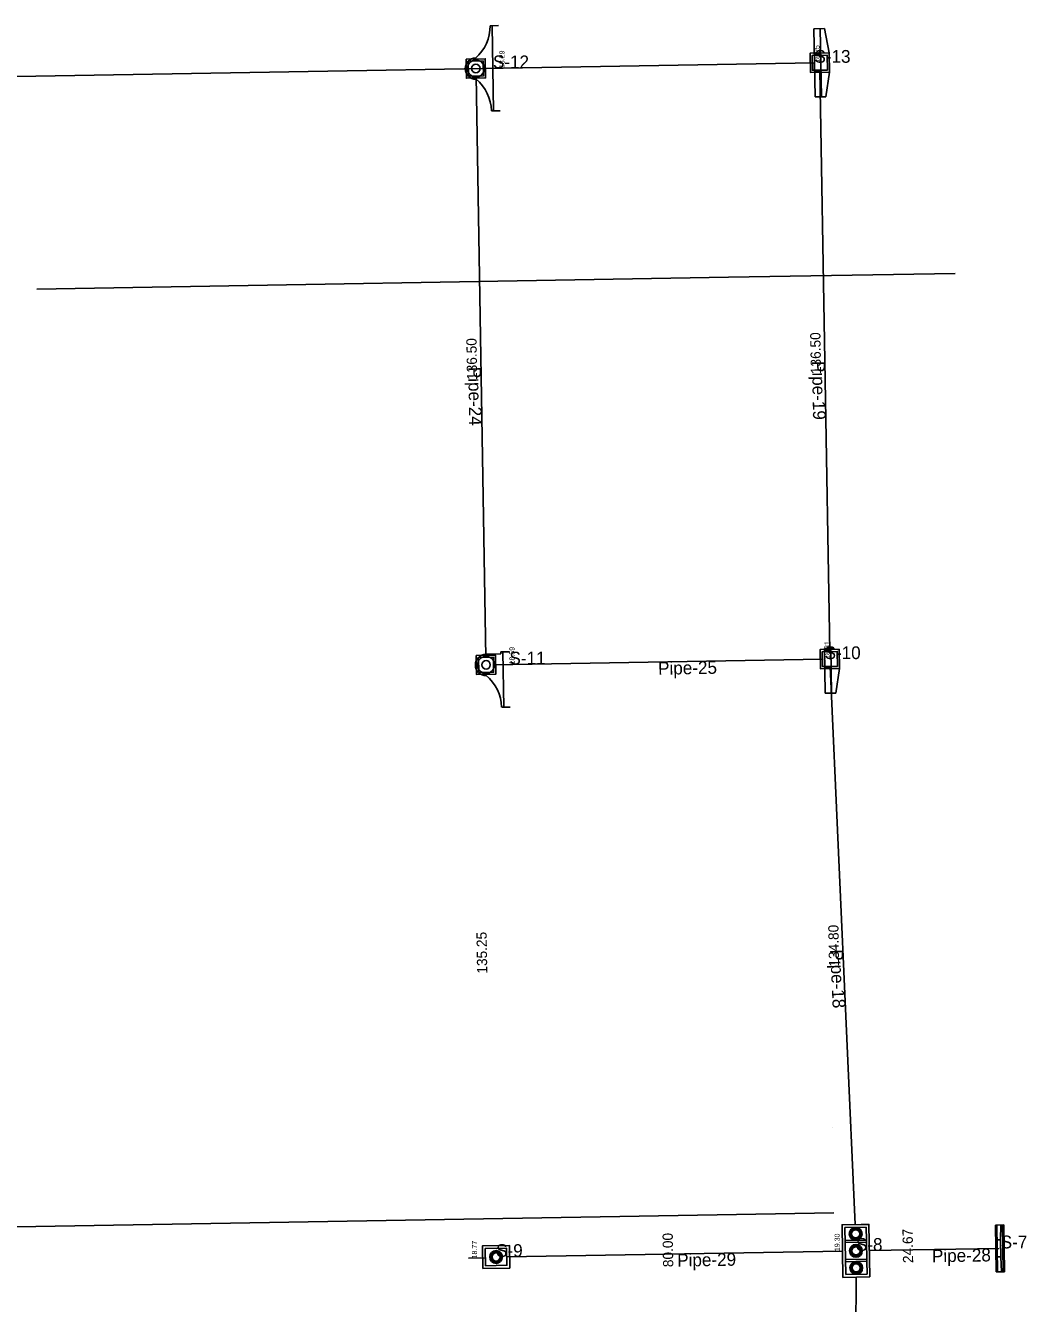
# Model space of a CAD drawing. Extents: x 925371 to 925937, y 853654 to 858024.
# Drawn here: x 925658.7 to 925893.7, y 853987.9 to 854287.9 of the extents above; entities that cross this region are included whole.
import ezdxf

# ---------------------------------------------------------------- set-up
doc = ezdxf.new("R2010")
doc.units = 0
for name, color, linetype in [('Endwall', 7, 'Continuous'), ('GPKDrBack_dp', 7, 'Continuous'), ('GPKDrBottom_dp', 7, 'Continuous'), ('GPKDrCellIns_dp', 7, 'Continuous'), ('GPKDrCentroid_dp', 7, 'Continuous'), ('GPKDrFront_dp', 7, 'Continuous'), ('GPKDrPipe_dp', 7, 'Continuous'), ('GPKDrPipeCir_dp', 7, 'Continuous'), ('InletBottomJ', 7, 'Continuous'), ('InletBottomP', 7, 'Continuous'), ('InletCurb', 7, 'Continuous'), ('Manhole', 7, 'Continuous'), ('Miscellaneous5', 7, 'Continuous'), ('Miscellaneous6', 7, 'Continuous'), ('NonPlottingEle_dp', 7, 'Continuous'), ('PipeCulvert', 7, 'Continuous')]:
    doc.layers.add(name, color=color, linetype=linetype)

msp = doc.modelspace()

# ---------------------------------------------------------------- linework, layer by layer
at = {"layer": 'Endwall'}
for p, q in [((925886.44, 854006.34), (925888.44, 854006.38)), ((925886.44, 854006.34), (925886.62, 853995.34)), ((925886.77, 854006.35), (925886.96, 853995.35)), ((925887.69, 854006.36), (925887.66, 854002.86)), ((925888.1, 854006.37), (925888.29, 853995.37)), ((925888.44, 854006.38), (925888.62, 853995.38)), ((925886.83, 854002.85), (925887.66, 854002.86)), ((925887.66, 854002.86), (925887.73, 853998.86)), ((925886.9, 853998.85), (925887.73, 853998.86)), ((925887.73, 853998.86), (925887.88, 853995.36)), ((925886.62, 853995.34), (925888.62, 853995.38))]:
    msp.add_line(p, q, dxfattribs=at)
at = {"layer": 'GPKDrBack_dp'}
for p, q in [((925846.96, 854279.21), (925846.96, 854279.21)), ((925847.46, 854279.22), (925847.46, 854279.22)), ((925761.97, 854277.76), (925761.97, 854277.76)), ((925762.72, 854277.78), (925762.72, 854277.78)), ((925764.35, 854137.78), (925764.35, 854137.78)), ((925765.1, 854137.8), (925765.1, 854137.8)), ((925849.34, 854139.23), (925849.34, 854139.23)), ((925849.84, 854139.24), (925849.84, 854139.24)), ((925852.14, 854004.26), (925852.14, 854004.26)), ((925852.2, 854000.26), (925852.2, 854000.26)), ((925886.86, 854000.85), (925886.86, 854000.85)), ((925769.24, 853997.35), (925769.24, 853997.35)), ((925769.25, 853996.85), (925769.25, 853996.85)), ((925852.27, 853996.26), (925852.27, 853996.26))]:
    msp.add_line(p, q, dxfattribs=at)
at = {"layer": 'GPKDrBottom_dp'}
for p, q in [((925762.69, 854279.53), (925762.69, 854279.53)), ((925763.03, 854279.2), (925763.03, 854279.2)), ((925764.44, 854279.81), (925764.44, 854279.81)), ((925764.44, 854279.56), (925764.44, 854279.56)), ((925765.86, 854279.24), (925765.86, 854279.24)), ((925766.19, 854279.59), (925766.19, 854279.59)), ((925843.43, 854280.9), (925843.43, 854280.9)), ((925843.43, 854280.9), (925843.43, 854280.9)), ((925843.46, 854279.15), (925843.46, 854279.15)), ((925843.46, 854279.15), (925843.46, 854279.15)), ((925845.18, 854280.93), (925845.18, 854280.93)), ((925845.18, 854280.93), (925845.18, 854280.93)), ((925845.21, 854279.18), (925845.21, 854279.18)), ((925845.21, 854279.18), (925845.21, 854279.18)), ((925846.93, 854280.96), (925846.93, 854280.96)), ((925846.93, 854280.96), (925846.93, 854280.96)), ((925846.96, 854279.21), (925846.96, 854279.21)), ((925846.96, 854279.21), (925846.96, 854279.21)), ((925762.47, 854277.77), (925762.47, 854277.77)), ((925762.72, 854277.78), (925762.72, 854277.78)), ((925762.75, 854276.03), (925762.75, 854276.03)), ((925763.08, 854276.37), (925763.08, 854276.37)), ((925764.47, 854277.81), (925764.47, 854277.81)), ((925764.47, 854277.81), (925764.47, 854277.81)), ((925764.5, 854276.06), (925764.5, 854276.06)), ((925764.51, 854275.81), (925764.51, 854275.81)), ((925765.91, 854276.42), (925765.91, 854276.42)), ((925766.22, 854277.84), (925766.22, 854277.84)), ((925766.25, 854276.09), (925766.25, 854276.09)), ((925766.47, 854277.84), (925766.47, 854277.84)), ((925843.49, 854277.4), (925843.49, 854277.4)), ((925843.49, 854277.4), (925843.49, 854277.4)), ((925845.24, 854277.43), (925845.24, 854277.43)), ((925845.24, 854277.43), (925845.24, 854277.43)), ((925846.99, 854277.46), (925846.99, 854277.46)), ((925846.99, 854277.46), (925846.99, 854277.46)), ((925845.81, 854140.92), (925845.81, 854140.92)), ((925845.81, 854140.92), (925845.81, 854140.92)), ((925847.56, 854140.95), (925847.56, 854140.95)), ((925847.56, 854140.95), (925847.56, 854140.95)), ((925849.31, 854140.98), (925849.31, 854140.98)), ((925849.31, 854140.98), (925849.31, 854140.98)), ((925764.85, 854137.79), (925764.85, 854137.79)), ((925765.07, 854139.55), (925765.07, 854139.55)), ((925765.1, 854137.8), (925765.1, 854137.8)), ((925765.41, 854139.22), (925765.41, 854139.22)), ((925766.82, 854139.83), (925766.82, 854139.83)), ((925766.82, 854139.58), (925766.82, 854139.58)), ((925766.85, 854137.83), (925766.85, 854137.83)), ((925766.85, 854137.83), (925766.85, 854137.83)), ((925768.24, 854139.27), (925768.24, 854139.27)), ((925768.57, 854139.61), (925768.57, 854139.61)), ((925768.6, 854137.86), (925768.6, 854137.86)), ((925768.85, 854137.86), (925768.85, 854137.86)), ((925845.84, 854139.17), (925845.84, 854139.17)), ((925845.84, 854139.17), (925845.84, 854139.17)), ((925847.59, 854139.2), (925847.59, 854139.2)), ((925847.59, 854139.2), (925847.59, 854139.2)), ((925849.34, 854139.23), (925849.34, 854139.23)), ((925849.34, 854139.23), (925849.34, 854139.23)), ((925849.37, 854137.48), (925849.37, 854137.48)), ((925849.37, 854137.48), (925849.37, 854137.48)), ((925765.13, 854136.05), (925765.13, 854136.05)), ((925765.46, 854136.39), (925765.46, 854136.39)), ((925766.88, 854136.08), (925766.88, 854136.08)), ((925766.89, 854135.83), (925766.89, 854135.83)), ((925768.29, 854136.44), (925768.29, 854136.44)), ((925768.63, 854136.11), (925768.63, 854136.11)), ((925845.87, 854137.42), (925845.87, 854137.42)), ((925845.87, 854137.42), (925845.87, 854137.42)), ((925847.62, 854137.45), (925847.62, 854137.45)), ((925847.62, 854137.45), (925847.62, 854137.45)), ((925852.64, 854004.27), (925852.64, 854004.27)), ((925852.92, 854004.98), (925852.92, 854004.98)), ((925852.94, 854003.56), (925852.94, 854003.56)), ((925853.62, 854005.28), (925853.62, 854005.28)), ((925853.63, 854004.28), (925853.63, 854004.28)), ((925853.65, 854003.28), (925853.65, 854003.28)), ((925854.33, 854005), (925854.33, 854005)), ((925854.35, 854003.59), (925854.35, 854003.59)), ((925854.63, 854004.3), (925854.63, 854004.3)), ((925766.68, 854000.8), (925766.68, 854000.8)), ((925768.5, 853999.54), (925768.5, 853999.54)), ((925769.18, 854000.85), (925769.18, 854000.85)), ((925769.2, 853999.85), (925769.2, 853999.85)), ((925769.91, 853999.57), (925769.91, 853999.57)), ((925771.68, 854000.89), (925771.68, 854000.89)), ((925852.7, 854000.27), (925852.7, 854000.27)), ((925852.98, 854000.98), (925852.98, 854000.98)), ((925853.01, 853999.56), (925853.01, 853999.56)), ((925853.69, 854001.28), (925853.69, 854001.28)), ((925853.7, 854000.28), (925853.7, 854000.28)), ((925854.4, 854001), (925854.4, 854001)), ((925854.42, 853999.59), (925854.42, 853999.59)), ((925854.7, 854000.3), (925854.7, 854000.3)), ((925887.7, 854000.86), (925887.7, 854000.86)), ((925766.71, 853998.8), (925766.71, 853998.8)), ((925766.75, 853996.8), (925766.75, 853996.8)), ((925768.21, 853998.83), (925768.21, 853998.83)), ((925768.52, 853998.13), (925768.52, 853998.13)), ((925769.21, 853998.85), (925769.21, 853998.85)), ((925769.21, 853998.85), (925769.21, 853998.85)), ((925769.23, 853997.85), (925769.23, 853997.85)), ((925769.25, 853996.85), (925769.25, 853996.85)), ((925769.93, 853998.15), (925769.93, 853998.15)), ((925770.21, 853998.86), (925770.21, 853998.86)), ((925771.71, 853998.89), (925771.71, 853998.89)), ((925771.75, 853996.89), (925771.75, 853996.89)), ((925853.05, 853996.98), (925853.05, 853996.98)), ((925853.72, 853999.28), (925853.72, 853999.28)), ((925853.75, 853997.28), (925853.75, 853997.28)), ((925854.47, 853997), (925854.47, 853997)), ((925852.77, 853996.27), (925852.77, 853996.27)), ((925853.08, 853995.57), (925853.08, 853995.57)), ((925853.77, 853996.28), (925853.77, 853996.28)), ((925853.79, 853995.28), (925853.79, 853995.28)), ((925854.49, 853995.59), (925854.49, 853995.59)), ((925854.77, 853996.3), (925854.77, 853996.3))]:
    msp.add_line(p, q, dxfattribs=at)
at = {"layer": 'GPKDrCellIns_dp'}
for p, q in [((925843.96, 854279.16), (925843.96, 854279.16)), ((925845.21, 854279.18), (925845.21, 854279.18)), ((925764.47, 854277.81), (925764.47, 854277.81)), ((925769.97, 854277.9), (925769.97, 854277.9)), ((925766.85, 854137.83), (925766.85, 854137.83)), ((925772.35, 854137.92), (925772.35, 854137.92)), ((925846.34, 854139.18), (925846.34, 854139.18)), ((925847.59, 854139.2), (925847.59, 854139.2)), ((925853.63, 854004.28), (925853.63, 854004.28)), ((925853.7, 854000.28), (925853.7, 854000.28)), ((925887.7, 854000.86), (925887.7, 854000.86)), ((925769.21, 853998.85), (925769.21, 853998.85)), ((925769.21, 853998.85), (925769.21, 853998.85)), ((925853.77, 853996.28), (925853.77, 853996.28))]:
    msp.add_line(p, q, dxfattribs=at)
at = {"layer": 'GPKDrCentroid_dp'}
for p, q in [((925845.21, 854279.18), (925845.21, 854279.18)), ((925764.47, 854277.81), (925764.47, 854277.81)), ((925766.85, 854137.83), (925766.85, 854137.83)), ((925847.59, 854139.2), (925847.59, 854139.2)), ((925853.63, 854004.28), (925853.63, 854004.28)), ((925853.7, 854000.28), (925853.7, 854000.28)), ((925769.21, 853998.85), (925769.21, 853998.85)), ((925769.21, 853998.85), (925769.21, 853998.85)), ((925853.77, 853996.28), (925853.77, 853996.28))]:
    msp.add_line(p, q, dxfattribs=at)
at = {"layer": 'GPKDrFront_dp'}
for p, q in [((925843.46, 854279.15), (925843.46, 854279.15)), ((925843.96, 854279.16), (925843.96, 854279.16)), ((925766.22, 854277.84), (925766.22, 854277.84)), ((925769.97, 854277.9), (925769.97, 854277.9)), ((925768.6, 854137.86), (925768.6, 854137.86)), ((925772.35, 854137.92), (925772.35, 854137.92)), ((925845.84, 854139.17), (925845.84, 854139.17)), ((925846.34, 854139.18), (925846.34, 854139.18)), ((925855.13, 854004.31), (925855.13, 854004.31)), ((925769.18, 854000.85), (925769.18, 854000.85)), ((925769.19, 854000.35), (925769.19, 854000.35)), ((925855.2, 854000.31), (925855.2, 854000.31)), ((925887.7, 854000.86), (925887.7, 854000.86)), ((925855.27, 853996.31), (925855.27, 853996.31))]:
    msp.add_line(p, q, dxfattribs=at)
at = {"layer": 'GPKDrPipe_dp'}
for p, q in [((925762.63, 854278.58), (925762.63, 854278.58)), ((925763.05, 854279.22), (925763.05, 854279.22)), ((925763.69, 854279.65), (925763.69, 854279.65)), ((925764.44, 854279.81), (925764.44, 854279.81)), ((925764.44, 854279.56), (925764.44, 854279.56)), ((925765.25, 854279.65), (925765.25, 854279.65)), ((925765.88, 854279.22), (925765.88, 854279.22)), ((925766.31, 854278.59), (925766.31, 854278.59)), ((925843.46, 854279.15), (925843.46, 854279.15)), ((925843.46, 854279.15), (925843.46, 854279.15)), ((925845.18, 854280.93), (925845.18, 854280.93)), ((925845.18, 854280.93), (925845.18, 854280.93)), ((925846.96, 854279.21), (925846.96, 854279.21)), ((925846.96, 854279.21), (925846.96, 854279.21)), ((925762.47, 854277.77), (925762.47, 854277.77)), ((925762.63, 854277.02), (925762.63, 854277.02)), ((925762.72, 854277.78), (925762.72, 854277.78)), ((925763.06, 854276.39), (925763.06, 854276.39)), ((925763.7, 854275.96), (925763.7, 854275.96)), ((925764.5, 854276.06), (925764.5, 854276.06)), ((925764.51, 854275.81), (925764.51, 854275.81)), ((925765.25, 854275.97), (925765.25, 854275.97)), ((925765.89, 854276.4), (925765.89, 854276.4)), ((925766.22, 854277.84), (925766.22, 854277.84)), ((925766.32, 854277.03), (925766.32, 854277.03)), ((925766.47, 854277.84), (925766.47, 854277.84)), ((925845.24, 854277.43), (925845.24, 854277.43)), ((925845.24, 854277.43), (925845.24, 854277.43)), ((925847.56, 854140.95), (925847.56, 854140.95)), ((925847.56, 854140.95), (925847.56, 854140.95)), ((925764.85, 854137.79), (925764.85, 854137.79)), ((925765.01, 854138.6), (925765.01, 854138.6)), ((925765.1, 854137.8), (925765.1, 854137.8)), ((925765.43, 854139.24), (925765.43, 854139.24)), ((925766.07, 854139.67), (925766.07, 854139.67)), ((925766.82, 854139.83), (925766.82, 854139.83)), ((925766.82, 854139.58), (925766.82, 854139.58)), ((925767.63, 854139.67), (925767.63, 854139.67)), ((925768.26, 854139.24), (925768.26, 854139.24)), ((925768.6, 854137.86), (925768.6, 854137.86)), ((925768.69, 854138.61), (925768.69, 854138.61)), ((925768.85, 854137.86), (925768.85, 854137.86)), ((925845.84, 854139.17), (925845.84, 854139.17)), ((925845.84, 854139.17), (925845.84, 854139.17)), ((925849.34, 854139.23), (925849.34, 854139.23)), ((925849.34, 854139.23), (925849.34, 854139.23)), ((925765.01, 854137.04), (925765.01, 854137.04)), ((925765.44, 854136.41), (925765.44, 854136.41)), ((925766.08, 854135.98), (925766.08, 854135.98)), ((925766.88, 854136.08), (925766.88, 854136.08)), ((925766.89, 854135.83), (925766.89, 854135.83)), ((925767.63, 854135.99), (925767.63, 854135.99)), ((925768.27, 854136.42), (925768.27, 854136.42)), ((925768.7, 854137.05), (925768.7, 854137.05)), ((925847.62, 854137.45), (925847.62, 854137.45)), ((925847.62, 854137.45), (925847.62, 854137.45)), ((925769.18, 854000.85), (925769.18, 854000.85)), ((925887.36, 854000.86), (925887.36, 854000.86)), ((925766.71, 853998.8), (925766.71, 853998.8)), ((925769.25, 853996.85), (925769.25, 853996.85)), ((925771.71, 853998.89), (925771.71, 853998.89))]:
    msp.add_line(p, q, dxfattribs=at)
at = {"layer": 'GPKDrPipeCir_dp'}
for points in [[(925843.49, 854277.4), (925843.43, 854280.9), (925846.93, 854280.96), (925846.99, 854277.46)], [(925845.87, 854137.42), (925845.81, 854140.92), (925849.31, 854140.98), (925849.37, 854137.48)]]:
    msp.add_lwpolyline(points, close=True, dxfattribs=at)
for centre, radius in [((925764.47, 854277.81), 2), ((925766.85, 854137.83), 2), ((925853.63, 854004.28), 0.958), ((925769.21, 853998.85), 0.958), ((925853.7, 854000.28), 0.958), ((925853.77, 853996.28), 0.958)]:
    msp.add_circle(centre, radius, dxfattribs=at)
at = {"layer": 'InletBottomJ'}
for p, q in [((925856.11, 854005.83), (925851.11, 854005.74)), ((925856.16, 854002.83), (925856.11, 854005.83)), ((925856.16, 854002.83), (925851.16, 854002.74)), ((925856.17, 854002.33), (925856.16, 854002.83)), ((925856.17, 854002.33), (925851.17, 854002.24)), ((925856.24, 853998.33), (925856.17, 854002.33)), ((925856.24, 853998.33), (925851.24, 853998.24)), ((925856.25, 853997.83), (925851.25, 853997.74)), ((925856.25, 853997.83), (925856.24, 853998.33)), ((925856.3, 853994.83), (925856.25, 853997.83)), ((925856.3, 853994.83), (925851.3, 853994.74))]:
    msp.add_line(p, q, dxfattribs=at)
for points in [[(925856.97, 853994.17), (925850.64, 853994.06), (925850.43, 854006.4), (925856.76, 854006.5)], [(925851.3, 853994.74), (925851.11, 854005.74)], [(925856.97, 853994.17), (925856.76, 854006.5), (925854.92, 854006.47)]]:
    msp.add_lwpolyline(points, dxfattribs=at)
for points in [[(925766.09, 853996.13), (925772.43, 853996.23), (925772.34, 854001.57), (925766, 854001.46)], [(925766.68, 854000.8), (925766.75, 853996.8), (925771.75, 853996.89), (925771.68, 854000.89)]]:
    msp.add_lwpolyline(points, close=True, dxfattribs=at)
at = {"layer": 'InletBottomP'}
for points in [[(925847.42, 854281.47), (925847.5, 854276.97), (925843, 854276.89), (925842.92, 854281.39)], [(925762.18, 854280.02), (925762.26, 854275.52), (925766.76, 854275.6), (925766.68, 854280.09)], [(925766.19, 854279.59), (925762.69, 854279.53), (925762.75, 854276.03), (925766.25, 854276.09)], [(925843.43, 854280.9), (925846.93, 854280.96), (925846.99, 854277.46), (925843.49, 854277.4)], [(925849.8, 854141.49), (925849.88, 854136.99), (925845.38, 854136.91), (925845.3, 854141.41)], [(925845.81, 854140.92), (925849.31, 854140.98), (925849.37, 854137.48), (925845.87, 854137.42)], [(925764.56, 854140.04), (925764.64, 854135.54), (925769.14, 854135.62), (925769.06, 854140.12)], [(925768.57, 854139.61), (925765.07, 854139.55), (925765.13, 854136.05), (925768.63, 854136.11)]]:
    msp.add_lwpolyline(points, close=True, dxfattribs=at)
at = {"layer": 'InletCurb'}
for p, q in [((925767.8, 854287.86), (925769.8, 854287.9)), ((925768.64, 854267.88), (925768.3, 854287.87)), ((925846.32, 854287.2), (925843.82, 854287.16)), ((925844.1, 854271.16), (925843.82, 854287.16)), ((925845.6, 854271.18), (925845.32, 854287.18)), ((925847.42, 854281.47), (925846.32, 854287.2)), ((925847.42, 854281.47), (925847.5, 854276.97)), ((925843.93, 854281.11), (925845.43, 854281.13)), ((925843.99, 854277.2), (925845.49, 854277.23)), ((925847.5, 854276.97), (925846.6, 854271.2)), ((925846.6, 854271.2), (925844.1, 854271.16)), ((925768.14, 854267.87), (925770.14, 854267.9)), ((925772.3, 854140.92), (925770.3, 854140.89)), ((925770.3, 854140.89), (925770.31, 854140.39)), ((925771.02, 854127.9), (925770.8, 854140.89)), ((925846.3, 854141.68), (925848.3, 854141.71)), ((925846.48, 854131.18), (925846.3, 854141.68)), ((925846.31, 854141.13), (925847.81, 854141.15)), ((925847.98, 854131.21), (925847.8, 854141.7)), ((925848.3, 854141.71), (925848.3, 854141.46)), ((925848.3, 854141.46), (925849.8, 854141.49)), ((925849.8, 854141.49), (925849.88, 854136.99)), ((925770.31, 854140.39), (925766.81, 854140.33)), ((925846.37, 854137.22), (925847.87, 854137.25)), ((925849.88, 854136.99), (925848.98, 854131.22)), ((925848.98, 854131.22), (925846.48, 854131.18)), ((925770.52, 854127.89), (925772.52, 854127.92))]:
    msp.add_line(p, q, dxfattribs=at)
for centre in [(925764.47, 854277.81), (925766.85, 854137.83)]:
    msp.add_circle(centre, 1, dxfattribs=at)
for centre, radius, start, end in [((925757.8, 854287.79), 10, 311.512, 0.4025), ((925764.47, 854277.81), 2.5, 90.9741, 270.9741), ((925758.14, 854267.6), 10, 1.5458, 50.4363), ((925766.85, 854137.83), 2.5, 90.9741, 270.9741), ((925760.52, 854127.62), 10, 1.5458, 50.4363)]:
    msp.add_arc(centre, radius, start, end, dxfattribs=at)
at = {"layer": 'Manhole'}
for p, q in [((925853.59, 854005.33), (925853.59, 854005.53)), ((925853.64, 854005.34), (925853.64, 854005.53)), ((925852.38, 854004.29), (925852.58, 854004.29)), ((925852.39, 854004.24), (925852.58, 854004.24)), ((925852.72, 854005.13), (925852.86, 854005)), ((925852.75, 854005.17), (925852.9, 854005.03)), ((925852.75, 854003.4), (925852.89, 854003.54)), ((925852.78, 854003.37), (925852.92, 854003.51)), ((925853.63, 854003.03), (925853.63, 854003.23)), ((925853.68, 854003.03), (925853.68, 854003.23)), ((925854.35, 854005.06), (925854.48, 854005.2)), ((925854.37, 854003.53), (925854.52, 854003.4)), ((925854.38, 854005.02), (925854.52, 854005.16)), ((925854.41, 854003.57), (925854.55, 854003.43)), ((925854.69, 854004.33), (925854.88, 854004.33)), ((925854.69, 854004.27), (925854.89, 854004.28)), ((925768.44, 853999.56), (925768.3, 853999.7)), ((925768.48, 853999.6), (925768.33, 853999.73)), ((925769.17, 853999.9), (925769.17, 854000.1)), ((925769.22, 853999.9), (925769.22, 854000.1)), ((925769.93, 853999.62), (925770.06, 853999.76)), ((925769.96, 853999.59), (925770.1, 853999.73)), ((925852.45, 854000.29), (925852.65, 854000.29)), ((925852.45, 854000.24), (925852.65, 854000.24)), ((925852.79, 854001.13), (925852.93, 854001)), ((925852.82, 854001.17), (925852.96, 854001.03)), ((925852.82, 853999.4), (925852.95, 853999.55)), ((925852.85, 853999.37), (925852.99, 853999.51)), ((925853.66, 854001.33), (925853.66, 854001.53)), ((925853.71, 854001.34), (925853.71, 854001.53)), ((925854.42, 854001.06), (925854.55, 854001.2)), ((925854.44, 853999.53), (925854.58, 853999.4)), ((925854.45, 854001.02), (925854.59, 854001.16)), ((925854.48, 853999.57), (925854.62, 853999.43)), ((925854.75, 854000.33), (925854.95, 854000.33)), ((925854.75, 854000.28), (925854.95, 854000.28)), ((925768.16, 853998.86), (925767.96, 853998.85)), ((925768.16, 853998.8), (925767.96, 853998.8)), ((925768.33, 853997.97), (925768.46, 853998.11)), ((925768.36, 853997.93), (925768.5, 853998.07)), ((925769.21, 853997.6), (925769.21, 853997.8)), ((925769.26, 853997.6), (925769.26, 853997.8)), ((925770.09, 853997.96), (925769.95, 853998.1)), ((925770.13, 853998), (925769.99, 853998.13)), ((925770.46, 853998.89), (925770.27, 853998.89)), ((925770.46, 853998.84), (925770.27, 853998.84)), ((925852.85, 853997.13), (925853, 853997)), ((925852.89, 853997.17), (925853.03, 853997.03)), ((925853.7, 853999.03), (925853.69, 853999.23)), ((925853.73, 853997.34), (925853.72, 853997.53)), ((925853.75, 853999.03), (925853.75, 853999.23)), ((925853.78, 853997.34), (925853.78, 853997.53)), ((925854.48, 853997.06), (925854.62, 853997.2)), ((925854.52, 853997.02), (925854.66, 853997.16)), ((925852.52, 853996.29), (925852.72, 853996.29)), ((925852.52, 853996.24), (925852.72, 853996.24)), ((925852.88, 853995.4), (925853.02, 853995.55)), ((925852.92, 853995.37), (925853.06, 853995.51)), ((925853.77, 853995.03), (925853.76, 853995.23)), ((925853.82, 853995.03), (925853.81, 853995.23)), ((925854.51, 853995.53), (925854.65, 853995.4)), ((925854.55, 853995.57), (925854.69, 853995.43)), ((925854.82, 853996.33), (925855.02, 853996.33)), ((925854.82, 853996.28), (925855.02, 853996.28))]:
    msp.add_line(p, q, dxfattribs=at)
for centre, radius in [((925853.63, 854004.28), 1.5), ((925853.63, 854004.28), 1.25), ((925853.63, 854004.28), 1.05), ((925853.63, 854004.28), 1), ((925769.21, 853998.85), 1.5), ((925769.21, 853998.85), 1.25), ((925769.21, 853998.85), 1.05), ((925769.21, 853998.85), 1), ((925853.7, 854000.28), 1.5), ((925853.7, 854000.28), 1.25), ((925853.7, 854000.28), 1.05), ((925853.7, 854000.28), 1), ((925853.77, 853996.28), 1.5), ((925853.77, 853996.28), 1.25), ((925853.77, 853996.28), 1.05), ((925853.77, 853996.28), 1)]:
    msp.add_circle(centre, radius, dxfattribs=at)
at = {"layer": 'Miscellaneous5'}
msp.add_line((925848.55, 854009.2), (925537.21, 854003.9), dxfattribs=at)
at = {"layer": 'Miscellaneous6'}
for p, q in [((925843.96, 854279.16), (925635.68, 854275.62)), ((925848.21, 854029.19), (925848.21, 854029.19))]:
    msp.add_line(p, q, dxfattribs=at)
at = {"layer": 'NonPlottingEle_dp'}
for q in [(925661.4, 854226.05), (925876.98, 854229.71)]:
    msp.add_line((925823.81, 854228.81), q, dxfattribs=at)
at = {"layer": 'PipeCulvert'}
for p, q in [((925764.5, 854276.06), (925766.82, 854139.58)), ((925845.24, 854277.43), (925847.56, 854140.95)), ((925768.6, 854137.86), (925845.84, 854139.17)), ((925847.62, 854137.45), (925853.55, 854006.45)), ((925771.71, 853998.89), (925850.54, 854000.23)), ((925856.87, 854000.34), (925887.36, 854000.86)), ((925766.72, 853998.65), (925762.72, 853998.59)), ((925852.93, 853825), (925853.77, 853994.12))]:
    msp.add_line(p, q, dxfattribs=at)

# ---------------------------------------------------------------- texts
at = {"layer": 'NonPlottingEle_dp'}
for s, height, rotation, p in [('18.29', 1.2, 90, (925771.18, 854277.9)), ('18.25', 1.2, 90, (925845.16, 854279.15)), ('136.50', 2.4, 90.9741, (925845.52, 854206.1)), ('136.50', 2.4, 90.9741, (925764.78, 854204.73)), ('Pipe-24', 3, 270.9741, (925762.66, 854207.77)), ('Pipe-19', 3, 270.9741, (925843.4, 854209.14)), ('18.59', 1.2, 90, (925773.54, 854137.92)), ('18.81', 1.2, 90, (925847.52, 854139.23)), ('Pipe-25', 3, 0.974, (925807.27, 854135.51)), ('135.25', 2.4, 90.9741, (925767.15, 854065.37)), ('134.80', 2.4, 90.9741, (925849.76, 854067.03)), ('Pipe-18', 3, 272.5922, (925847.63, 854070.98)), ('80.00', 2.4, 90.9741, (925810.82, 853996.48)), ('19.30', 1.2, 90, (925849.89, 854000.2)), ('24.67', 2.4, 90.9741, (925867.15, 853997.44)), ('18.77', 1.2, 90, (925764.74, 853998.5)), ('Pipe-29', 3, 0.9741, (925811.76, 853996.57)), ('Pipe-28', 3, 0.9741, (925871.58, 853997.59))]:
    msp.add_text(s, height=height, rotation=rotation, dxfattribs=at).set_placement(p)
for s, p in [('S-13', (925843.96, 854279.16)), ('S-12', (925768.47, 854277.87)), ('S-11', (925772.35, 854137.92)), ('S-10', (925846.34, 854139.18)), ('S-8', (925853.7, 854000.28)), ('S-7', (925887.7, 854000.86)), ('S-9', (925769.21, 853998.85))]:
    msp.add_text(s, height=3, dxfattribs=at).set_placement(p)

doc.saveas('drawing.dxf')
